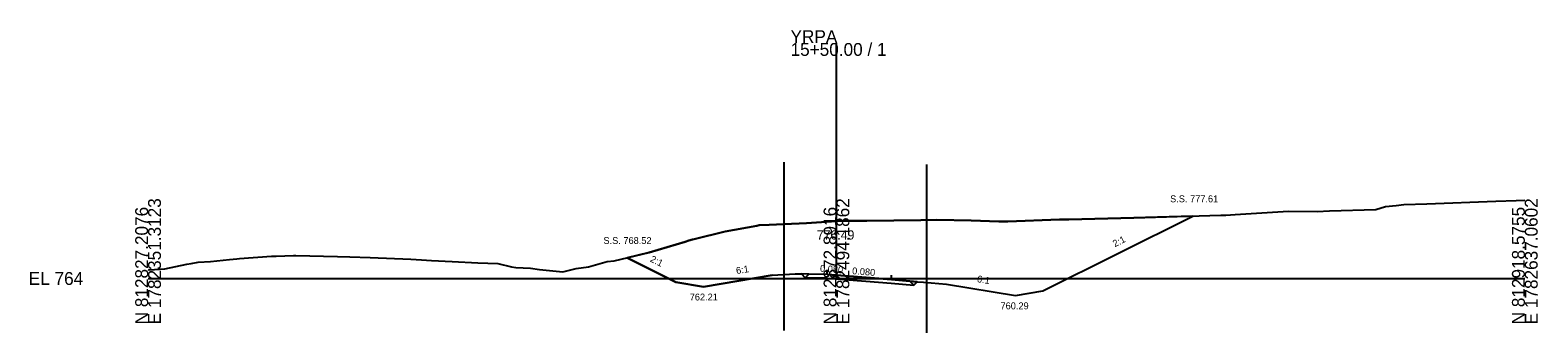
# Model space of a CAD drawing. Extents: x -26 to 2603, y -14 to 9545.
# Drawn here: x -25.7 to 302.8, y 5488.2 to 5554.1 of the extents above; entities that cross this region are included whole.
import ezdxf

# ---------------------------------------------------------------- set-up
doc = ezdxf.new("R2010")
doc.units = 0
for name, color, linetype in [('Exist Cross Section Cell', 7, 'Continuous'), ('Exist XS Center Line Elevation Label', 7, 'Continuous'), ('Exist XS Ground Line', 7, 'Continuous'), ('Prop XS Ditch Slope Text', 7, 'Continuous'), ('Prop XS Ditch Standard Text', 7, 'Continuous'), ('Prop XS Dump Level', 7, 'Continuous'), ('Prop XS Earthwork Shape', 7, 'Continuous'), ('Prop XS EOT Tick Mark', 7, 'Continuous'), ('Prop XS Exc Vertical Line 1', 7, 'Continuous'), ('Prop XS Exc Vertical Line 2', 7, 'Continuous'), ('Prop XS Finish Grade', 7, 'Continuous'), ('Prop XS Finish Grade Earthwork', 7, 'Continuous'), ('Prop XS Finish Grade Paved Shoulder', 7, 'Continuous'), ('Prop XS Finish Grade Pavement', 7, 'Continuous'), ('Prop XS Hydro Typical Ditch Data', 7, 'Continuous'), ('Prop XS Pvmt Edge Slope', 7, 'Continuous'), ('Prop XS SE Text', 7, 'Continuous'), ('Prop XS Side Slope Text', 7, 'Continuous'), ('Prop XS SS Elevation Text', 7, 'Continuous'), ('Prop XS Subgrade Earthwork', 7, 'Continuous'), ('Scratch_Level_6', 7, 'Continuous')]:
    doc.layers.add(name, color=color, linetype=linetype)

msp = doc.modelspace()

# ---------------------------------------------------------------- linework, layer by layer
at = {"layer": 'Exist Cross Section Cell'}
for p, q in [((150, 5500), (150, 5551.31)), ((0, 5500), (150, 5500)), ((150, 5500), (300, 5500))]:
    msp.add_line(p, q, dxfattribs=at)
at = {"layer": 'Exist XS Ground Line'}
for p, q in [((272, 5515.89), (273.63, 5516.11)), ((273.63, 5516.11), (278.63, 5516.26)), ((278.63, 5516.26), (293.65, 5516.83)), ((293.65, 5516.83), (298.15, 5517.01)), ((298.15, 5517.01), (300, 5517.1)), ((187.35, 5512.43), (198.61, 5512.86)), ((198.61, 5512.86), (200.62, 5512.87)), ((200.62, 5512.87), (203.48, 5512.96)), ((203.48, 5512.96), (214.83, 5513.23)), ((214.83, 5513.23), (233.77, 5513.79)), ((233.77, 5513.79), (234.82, 5513.83)), ((234.82, 5513.83), (236.85, 5513.98)), ((236.85, 5513.98), (248.49, 5514.66)), ((248.49, 5514.66), (254.78, 5514.61)), ((254.78, 5514.61), (257.42, 5514.71)), ((257.42, 5514.71), (267.51, 5515.05)), ((267.51, 5515.05), (269.67, 5515.68)), ((269.67, 5515.68), (272, 5515.89)), ((118.98, 5508.56), (125.77, 5510.23)), ((125.77, 5510.23), (132.68, 5511.5)), ((132.68, 5511.5), (133.18, 5511.6)), ((133.18, 5511.6), (135.34, 5511.68)), ((135.34, 5511.68), (143.51, 5512.03)), ((143.51, 5512.03), (150, 5512.49)), ((150, 5512.49), (150.87, 5512.56)), ((150.87, 5512.56), (156.62, 5512.59)), ((156.62, 5512.59), (168.39, 5512.74)), ((168.39, 5512.74), (171.9, 5512.77)), ((171.9, 5512.77), (179.33, 5512.6)), ((179.33, 5512.6), (185.39, 5512.39)), ((185.39, 5512.39), (187.35, 5512.43)), ((109.21, 5505.63), (117.01, 5508.02)), ((117.01, 5508.02), (117.8, 5508.27)), ((117.8, 5508.27), (118.64, 5508.49)), ((118.64, 5508.49), (118.98, 5508.56)), ((3.65, 5502.1), (8.48, 5503.1)), ((8.48, 5503.1), (9.38, 5503.23)), ((9.38, 5503.23), (10.93, 5503.53)), ((10.93, 5503.53), (13.63, 5503.67)), ((13.63, 5503.67), (17.73, 5504.13)), ((17.73, 5504.13), (19.33, 5504.26)), ((19.33, 5504.26), (19.92, 5504.34)), ((19.92, 5504.34), (26.93, 5504.83)), ((26.93, 5504.83), (27.92, 5504.86)), ((27.92, 5504.86), (31.7, 5504.98)), ((31.7, 5504.98), (32.23, 5505)), ((32.23, 5505), (41.28, 5504.77)), ((41.28, 5504.77), (43.95, 5504.71)), ((43.95, 5504.71), (48.37, 5504.55)), ((48.37, 5504.55), (57.28, 5504.24)), ((57.28, 5504.24), (59.59, 5504.09)), ((59.59, 5504.09), (61.77, 5503.95)), ((61.77, 5503.95), (66.26, 5503.69)), ((66.26, 5503.69), (71.83, 5503.42)), ((71.83, 5503.42), (76.21, 5503.23)), ((76.21, 5503.23), (79.21, 5502.51)), ((96, 5502.51), (100.01, 5503.7)), ((100.01, 5503.7), (101.57, 5503.88)), ((101.57, 5503.88), (109.21, 5505.63)), ((0, 5501.96), (0.27, 5501.9)), ((0.27, 5501.9), (3.65, 5502.1)), ((79.21, 5502.51), (80.16, 5502.4)), ((80.16, 5502.4), (83.3, 5502.26)), ((83.3, 5502.26), (85.29, 5501.98)), ((85.29, 5501.98), (90.39, 5501.44)), ((90.39, 5501.44), (93.32, 5502.17)), ((93.32, 5502.17), (96, 5502.51))]:
    msp.add_line(p, q, dxfattribs=at)
at = {"layer": 'Prop XS Dump Level'}
for p, q in [((148, 5500.87), (150, 5500.71)), ((150, 5500.71), (162, 5499.75))]:
    msp.add_line(p, q, dxfattribs=at)
at = {"layer": 'Prop XS Earthwork Shape'}
msp.add_lwpolyline([(161.94, 5498.96), (166.86, 5498.56), (167.6, 5499.3), (169, 5499.19), (174, 5498.79), (189, 5496.29), (195, 5497.29), (227.64, 5513.61), (214.83, 5513.23), (203.48, 5512.96), (200.62, 5512.87), (198.61, 5512.86), (187.35, 5512.43), (185.39, 5512.39), (179.33, 5512.6), (171.9, 5512.77), (168.39, 5512.74), (156.62, 5512.59), (150.87, 5512.56), (150, 5512.49), (143.51, 5512.03), (135.34, 5511.68), (133.18, 5511.6), (132.68, 5511.5), (125.77, 5510.23), (118.98, 5508.56), (118.64, 5508.49), (117.8, 5508.27), (117.01, 5508.02), (109.21, 5505.63), (104.37, 5504.52), (115, 5499.21), (121, 5498.21), (136, 5500.71), (141, 5501.01), (142.42, 5500.98), (143.22, 5500.17), (147.96, 5500.08), (149.94, 5499.92)], close=True, dxfattribs=at)
at = {"layer": 'Prop XS EOT Tick Mark'}
for p, q in [((148, 5500.87), (148, 5501.87)), ((162, 5499.75), (162, 5500.75))]:
    msp.add_line(p, q, dxfattribs=at)
at = {"layer": 'Prop XS Exc Vertical Line 1'}
msp.add_line((138.63, 5488.64), (138.63, 5525.32), dxfattribs=at)
at = {"layer": 'Prop XS Exc Vertical Line 2'}
msp.add_line((169.69, 5488.16), (169.69, 5524.84), dxfattribs=at)
at = {"layer": 'Prop XS Finish Grade'}
for p, q in [((144, 5500.95), (142.42, 5500.98)), ((166, 5499.43), (167.6, 5499.3))]:
    msp.add_line(p, q, dxfattribs=at)
at = {"layer": 'Prop XS Finish Grade Earthwork'}
for p, q in [((195, 5497.29), (227.64, 5513.61)), ((115, 5499.21), (104.37, 5504.52)), ((136, 5500.71), (121, 5498.21)), ((136, 5500.71), (141, 5501.01)), ((141, 5501.01), (142.42, 5500.98)), ((121, 5498.21), (115, 5499.21)), ((167.6, 5499.3), (169, 5499.19)), ((169, 5499.19), (174, 5498.79)), ((174, 5498.79), (189, 5496.29)), ((189, 5496.29), (195, 5497.29))]:
    msp.add_line(p, q, dxfattribs=at)
at = {"layer": 'Prop XS Finish Grade Paved Shoulder'}
for p, q in [((148, 5500.87), (144, 5500.95)), ((162, 5499.75), (166, 5499.43))]:
    msp.add_line(p, q, dxfattribs=at)
at = {"layer": 'Prop XS Finish Grade Pavement'}
for p, q in [((148, 5500.87), (150, 5500.71)), ((150, 5500.71), (162, 5499.75))]:
    msp.add_line(p, q, dxfattribs=at)
at = {"layer": 'Prop XS Hydro Typical Ditch Data'}
for p, q in [((115, 5499.21), (104.37, 5504.52)), ((121, 5498.21), (115, 5499.21))]:
    msp.add_line(p, q, dxfattribs=at)
at = {"layer": 'Prop XS Pvmt Edge Slope'}
for p, q in [((144, 5500.95), (143.22, 5500.17)), ((166, 5499.43), (166.86, 5498.56))]:
    msp.add_line(p, q, dxfattribs=at)
at = {"layer": 'Prop XS Subgrade Earthwork'}
for p, q in [((143.22, 5500.17), (142.42, 5500.98)), ((147.96, 5500.08), (143.22, 5500.17)), ((147.96, 5500.08), (149.94, 5499.92)), ((149.94, 5499.92), (161.94, 5498.96)), ((161.94, 5498.96), (166.86, 5498.56)), ((166.86, 5498.56), (167.6, 5499.3))]:
    msp.add_line(p, q, dxfattribs=at)
at = {"layer": 'Scratch_Level_6'}
msp.add_lwpolyline([(144, 5500.95), (142.42, 5500.98), (143.22, 5500.17), (147.96, 5500.08), (149.94, 5499.92), (161.94, 5498.96), (166.86, 5498.56), (167.6, 5499.3), (166, 5499.43), (162, 5499.75), (150, 5500.71), (148, 5500.87)], close=True, dxfattribs=at)

# ---------------------------------------------------------------- texts
at = {"layer": 'Exist Cross Section Cell'}
for s, p in [('YRPA', (140, 5551.31)), ('15+50.00 / 1', (140, 5548.51)), ('EL 764', (-26, 5498.6))]:
    msp.add_text(s, height=2.8, dxfattribs=at).set_placement(p)
for s, p in [('E 1782351.3123', (2.8, 5490)), ('E 1782494.1862', (152.8, 5490)), ('E 1782637.0602', (302.8, 5490)), ('N 812827.2076', (0, 5490)), ('N 812872.8916', (150, 5490)), ('N 812918.5755', (300, 5490))]:
    msp.add_text(s, height=2.8, rotation=90, dxfattribs=at).set_placement(p)
at = {"layer": 'Exist XS Center Line Elevation Label'}
msp.add_text('776.49', height=2, dxfattribs=at).set_placement((145.73, 5508.49))
at = {"layer": 'Prop XS Ditch Slope Text'}
for rotation, p in [(9.4623, (128.25, 5500.94)), (350.5377, (180.55, 5499.22))]:
    msp.add_text('6:1', height=1.5, rotation=rotation, dxfattribs=at).set_placement(p)
at = {"layer": 'Prop XS Ditch Standard Text'}
for s, p in [('762.21', (118.03, 5495.21)), ('760.29', (185.75, 5493.29))]:
    msp.add_text(s, height=1.5, dxfattribs=at).set_placement(p)
at = {"layer": 'Prop XS Dump Level'}
for p in [(136, 5500.67), (174, 5498.75)]:
    msp.add_text('Case4', height=0.04, dxfattribs=at).set_placement(p)
at = {"layer": 'Prop XS SE Text'}
for p in [(146.38, 5501.5), (153.38, 5500.94)]:
    msp.add_text('0.080', height=1.5, rotation=355.4261, dxfattribs=at).set_placement(p)
at = {"layer": 'Prop XS Side Slope Text'}
for rotation, p in [(26.5651, (210.65, 5506.79)), (333.4349, (109.27, 5503.75))]:
    msp.add_text('2:1', height=1.5, rotation=rotation, dxfattribs=at).set_placement(p)
at = {"layer": 'Prop XS SS Elevation Text'}
for s, p in [('S.S. 777.61', (222.71, 5516.61)), ('S.S. 768.52', (99.23, 5507.52))]:
    msp.add_text(s, height=1.5, dxfattribs=at).set_placement(p)

doc.saveas('drawing.dxf')
